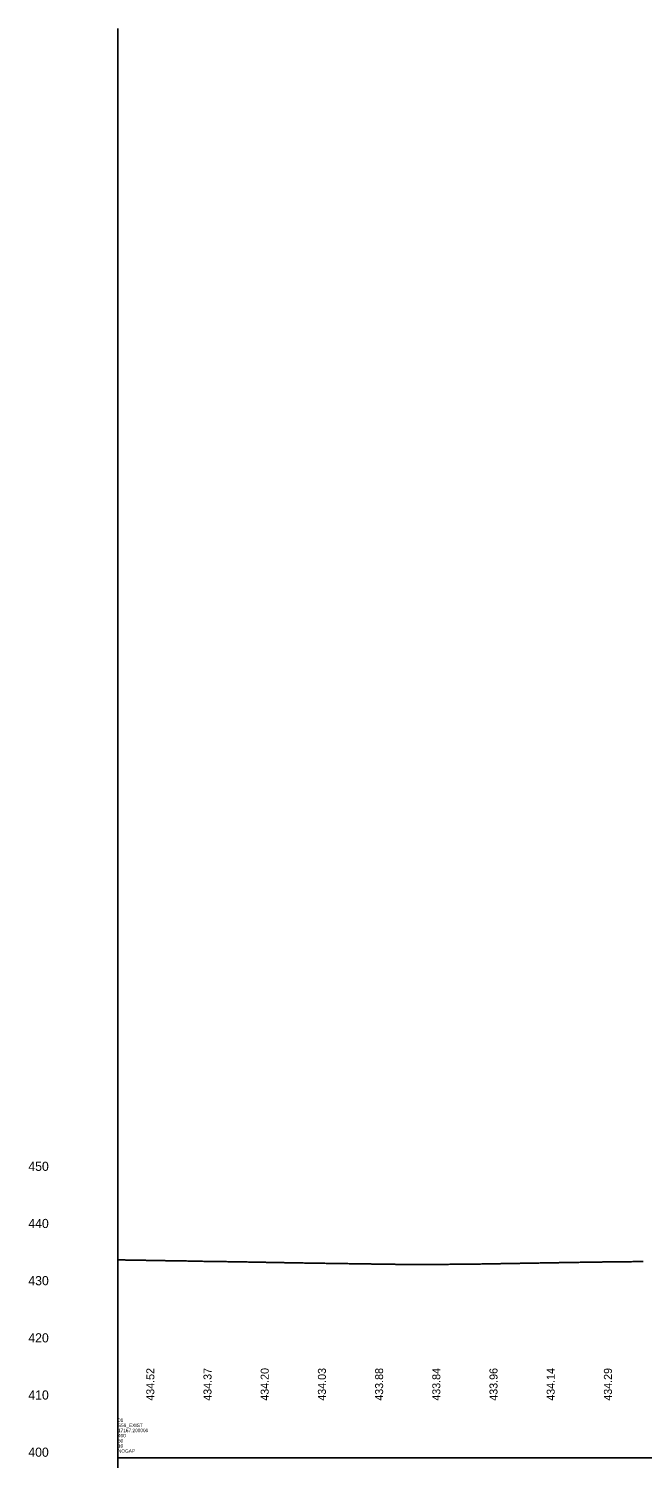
# Model space of a CAD drawing. Extents: x 1904865 to 1906752, y 1106408 to 1110518.
# Drawn here: x 1905174 to 1905711, y 1107657 to 1108908 of the extents above; entities that cross this region are included whole.
import ezdxf

# ---------------------------------------------------------------- set-up
doc = ezdxf.new("R2010")
doc.units = 0
for name, color, linetype in [('RD_DDB_ElevTX', 7, 'Continuous'), ('RD_DDB_Profile_EX', 7, 'Continuous'), ('RD_DDB_StripGrade', 7, 'Continuous'), ('RD_GPK_Profile_Cell', 7, 'Continuous')]:
    doc.layers.add(name, color=color, linetype=linetype)

msp = doc.modelspace()

# ---------------------------------------------------------------- linework, layer by layer
at = {"layer": 'RD_DDB_Profile_EX'}
for points in [[(1905252.2, 1107830.8), (1905253.2, 1107830.7), (1905254.2, 1107830.7), (1905255.2, 1107830.7), (1905256.2, 1107830.7), (1905257.2, 1107830.7), (1905258.2, 1107830.7), (1905259.2, 1107830.6), (1905260.2, 1107830.6), (1905261.2, 1107830.6), (1905262.2, 1107830.6), (1905263.2, 1107830.6), (1905264.2, 1107830.6), (1905265.2, 1107830.5), (1905266.2, 1107830.5), (1905267.2, 1107830.5), (1905268.2, 1107830.5), (1905269.2, 1107830.5), (1905270.2, 1107830.5), (1905271.2, 1107830.4), (1905272.2, 1107830.4), (1905273.2, 1107830.4), (1905274.2, 1107830.4), (1905275.2, 1107830.4), (1905276.2, 1107830.4), (1905277.2, 1107830.3), (1905278.2, 1107830.3), (1905279.2, 1107830.3), (1905280.2, 1107830.3), (1905281.2, 1107830.3), (1905282.2, 1107830.2), (1905283.2, 1107830.2), (1905284.2, 1107830.2), (1905285.2, 1107830.2), (1905286.2, 1107830.2), (1905287.2, 1107830.2), (1905288.2, 1107830.1), (1905289.2, 1107830.1), (1905290.2, 1107830.1), (1905291.2, 1107830.1), (1905292.2, 1107830.1), (1905293.2, 1107830.1), (1905294.2, 1107830), (1905295.2, 1107830), (1905296.2, 1107830), (1905297.2, 1107830), (1905298.2, 1107830), (1905299.2, 1107830), (1905300.2, 1107829.9), (1905301.2, 1107829.9), (1905302.2, 1107829.9), (1905303.2, 1107829.9), (1905304.2, 1107829.9), (1905305.2, 1107829.9), (1905306.2, 1107829.8), (1905307.2, 1107829.8), (1905308.2, 1107829.8), (1905309.2, 1107829.8), (1905310.2, 1107829.8), (1905311.2, 1107829.8), (1905312.2, 1107829.8), (1905313.2, 1107829.7), (1905314.2, 1107829.7), (1905315.2, 1107829.7), (1905316.2, 1107829.7), (1905317.2, 1107829.7), (1905318.2, 1107829.7), (1905319.2, 1107829.7), (1905320.2, 1107829.6), (1905321.2, 1107829.6), (1905322.2, 1107829.6), (1905323.2, 1107829.6), (1905324.2, 1107829.6), (1905325.2, 1107829.6), (1905326.2, 1107829.6), (1905327.2, 1107829.5), (1905328.2, 1107829.5), (1905329.2, 1107829.5), (1905330.2, 1107829.5), (1905331.2, 1107829.5), (1905332.2, 1107829.5), (1905333.2, 1107829.5), (1905334.2, 1107829.4), (1905335.2, 1107829.4), (1905336.2, 1107829.4), (1905337.2, 1107829.4), (1905338.2, 1107829.4), (1905339.2, 1107829.4), (1905340.2, 1107829.4), (1905341.2, 1107829.3), (1905342.2, 1107829.3), (1905343.2, 1107829.3), (1905344.2, 1107829.3), (1905345.2, 1107829.3), (1905346.2, 1107829.3), (1905347.2, 1107829.3), (1905348.2, 1107829.2), (1905349.2, 1107829.2), (1905350.2, 1107829.2), (1905351.2, 1107829.2), (1905352.2, 1107829.2)], [(1905352.2, 1107829.2), (1905353.2, 1107829.2), (1905354.2, 1107829.2), (1905355.2, 1107829.1), (1905356.2, 1107829.1), (1905357.2, 1107829.1), (1905358.2, 1107829.1), (1905359.2, 1107829.1), (1905360.2, 1107829.1), (1905361.2, 1107829), (1905362.2, 1107829), (1905363.2, 1107829), (1905364.2, 1107829), (1905365.2, 1107829), (1905366.2, 1107828.9), (1905367.2, 1107828.9), (1905368.2, 1107828.9), (1905369.2, 1107828.9), (1905370.2, 1107828.9), (1905371.2, 1107828.8), (1905372.2, 1107828.8), (1905373.2, 1107828.8), (1905374.2, 1107828.8), (1905375.2, 1107828.8), (1905376.2, 1107828.8), (1905377.2, 1107828.7), (1905378.2, 1107828.7), (1905379.2, 1107828.7), (1905380.2, 1107828.7), (1905381.2, 1107828.7), (1905382.2, 1107828.6), (1905383.2, 1107828.6), (1905384.2, 1107828.6), (1905385.2, 1107828.6), (1905386.2, 1107828.6), (1905387.2, 1107828.5), (1905388.2, 1107828.5), (1905389.2, 1107828.5), (1905390.2, 1107828.5), (1905391.2, 1107828.5), (1905392.2, 1107828.5), (1905393.2, 1107828.4), (1905394.2, 1107828.4), (1905395.2, 1107828.4), (1905396.2, 1107828.4), (1905397.2, 1107828.4), (1905398.2, 1107828.3), (1905399.2, 1107828.3), (1905400.2, 1107828.3), (1905401.2, 1107828.3), (1905402.2, 1107828.3), (1905403.2, 1107828.2), (1905404.2, 1107828.2), (1905405.2, 1107828.2), (1905406.2, 1107828.2), (1905407.2, 1107828.2), (1905408.2, 1107828.1), (1905409.2, 1107828.1), (1905410.2, 1107828.1), (1905411.2, 1107828.1), (1905412.2, 1107828.1), (1905413.2, 1107828.1), (1905414.2, 1107828.1), (1905415.2, 1107828), (1905416.2, 1107828), (1905417.2, 1107828), (1905418.2, 1107828), (1905419.2, 1107828), (1905420.2, 1107828), (1905421.2, 1107827.9), (1905422.2, 1107827.9), (1905423.2, 1107827.9), (1905424.2, 1107827.9), (1905425.2, 1107827.9), (1905426.2, 1107827.9), (1905427.2, 1107827.9), (1905428.2, 1107827.8), (1905429.2, 1107827.8), (1905430.2, 1107827.8), (1905431.2, 1107827.8), (1905432.2, 1107827.8), (1905433.2, 1107827.8), (1905434.2, 1107827.7), (1905435.2, 1107827.7), (1905436.2, 1107827.7), (1905437.2, 1107827.7), (1905438.2, 1107827.7), (1905439.2, 1107827.7), (1905440.2, 1107827.7), (1905441.2, 1107827.6), (1905442.2, 1107827.6), (1905443.2, 1107827.6), (1905444.2, 1107827.6), (1905445.2, 1107827.6), (1905446.2, 1107827.6), (1905447.2, 1107827.5), (1905448.2, 1107827.5), (1905449.2, 1107827.5), (1905450.2, 1107827.5), (1905451.2, 1107827.5), (1905452.2, 1107827.5)], [(1905552.2, 1107827), (1905553.2, 1107827), (1905554.2, 1107827), (1905555.2, 1107827), (1905556.2, 1107827), (1905557.2, 1107827), (1905558.2, 1107827), (1905559.2, 1107827), (1905560.2, 1107827), (1905561.2, 1107827), (1905562.2, 1107827), (1905563.2, 1107827.1), (1905564.2, 1107827.1), (1905565.2, 1107827.1), (1905566.2, 1107827.1), (1905567.2, 1107827.1), (1905568.2, 1107827.1), (1905569.2, 1107827.1), (1905570.2, 1107827.2), (1905571.2, 1107827.2), (1905572.2, 1107827.2), (1905573.2, 1107827.2), (1905574.2, 1107827.2), (1905575.2, 1107827.2), (1905576.2, 1107827.3), (1905577.2, 1107827.3), (1905578.2, 1107827.3), (1905579.2, 1107827.3), (1905580.2, 1107827.3), (1905581.2, 1107827.4), (1905582.2, 1107827.4), (1905583.2, 1107827.4), (1905584.2, 1107827.4), (1905585.2, 1107827.4), (1905586.2, 1107827.4), (1905587.2, 1107827.5), (1905588.2, 1107827.5), (1905589.2, 1107827.5), (1905590.2, 1107827.5), (1905591.2, 1107827.5), (1905592.2, 1107827.5), (1905593.2, 1107827.6), (1905594.2, 1107827.6), (1905595.2, 1107827.6), (1905596.2, 1107827.6), (1905597.2, 1107827.6), (1905598.2, 1107827.7), (1905599.2, 1107827.7), (1905600.2, 1107827.7), (1905601.2, 1107827.7), (1905602.2, 1107827.7), (1905603.2, 1107827.7), (1905604.2, 1107827.8), (1905605.2, 1107827.8), (1905606.2, 1107827.8), (1905607.2, 1107827.8), (1905608.2, 1107827.8), (1905609.2, 1107827.9), (1905610.2, 1107827.9), (1905611.2, 1107827.9), (1905612.2, 1107827.9), (1905613.2, 1107827.9), (1905614.2, 1107827.9), (1905615.2, 1107828), (1905616.2, 1107828), (1905617.2, 1107828), (1905618.2, 1107828), (1905619.2, 1107828), (1905620.2, 1107828), (1905621.2, 1107828.1), (1905622.2, 1107828.1), (1905623.2, 1107828.1), (1905624.2, 1107828.1), (1905625.2, 1107828.1), (1905626.2, 1107828.2), (1905627.2, 1107828.2), (1905628.2, 1107828.2), (1905629.2, 1107828.2), (1905630.2, 1107828.2), (1905631.2, 1107828.2), (1905632.2, 1107828.3), (1905633.2, 1107828.3), (1905634.2, 1107828.3), (1905635.2, 1107828.3), (1905636.2, 1107828.3), (1905637.2, 1107828.3), (1905638.2, 1107828.4), (1905639.2, 1107828.4), (1905640.2, 1107828.4), (1905641.2, 1107828.4), (1905642.2, 1107828.4), (1905643.2, 1107828.4), (1905644.2, 1107828.5), (1905645.2, 1107828.5), (1905646.2, 1107828.5), (1905647.2, 1107828.5), (1905648.2, 1107828.5), (1905649.2, 1107828.5), (1905650.2, 1107828.6), (1905651.2, 1107828.6), (1905652.2, 1107828.6)], [(1905652.2, 1107828.6), (1905653.2, 1107828.6), (1905654.2, 1107828.6), (1905655.2, 1107828.6), (1905656.2, 1107828.7), (1905657.2, 1107828.7), (1905658.2, 1107828.7), (1905659.2, 1107828.7), (1905660.2, 1107828.7), (1905661.2, 1107828.7), (1905662.2, 1107828.8), (1905663.2, 1107828.8), (1905664.2, 1107828.8), (1905665.2, 1107828.8), (1905666.2, 1107828.8), (1905667.2, 1107828.8), (1905668.2, 1107828.8), (1905669.2, 1107828.9), (1905670.2, 1107828.9), (1905671.2, 1107828.9), (1905672.2, 1107828.9), (1905673.2, 1107828.9), (1905674.2, 1107828.9), (1905675.2, 1107828.9), (1905676.2, 1107829), (1905677.2, 1107829), (1905678.2, 1107829), (1905679.2, 1107829), (1905680.2, 1107829), (1905681.2, 1107829), (1905682.2, 1107829), (1905683.2, 1107829), (1905684.2, 1107829), (1905685.2, 1107829.1), (1905686.2, 1107829.1), (1905687.2, 1107829.1), (1905688.2, 1107829.1), (1905689.2, 1107829.1), (1905690.2, 1107829.1), (1905691.2, 1107829.1), (1905692.2, 1107829.1), (1905693.2, 1107829.2), (1905694.2, 1107829.2), (1905695.2, 1107829.2), (1905696.2, 1107829.2), (1905697.2, 1107829.2), (1905698.2, 1107829.2), (1905699.2, 1107829.2), (1905700.2, 1107829.2), (1905701.2, 1107829.2), (1905702.2, 1107829.3), (1905703.2, 1107829.3), (1905704.2, 1107829.3), (1905705.2, 1107829.3), (1905706.2, 1107829.3), (1905707.2, 1107829.3), (1905708.2, 1107829.3), (1905709.2, 1107829.3), (1905710.2, 1107829.4), (1905711.2, 1107829.4)], [(1905452.2, 1107827.5), (1905453.2, 1107827.5), (1905454.2, 1107827.4), (1905455.2, 1107827.4), (1905456.2, 1107827.4), (1905457.2, 1107827.4), (1905458.2, 1107827.4), (1905459.2, 1107827.4), (1905460.2, 1107827.3), (1905461.2, 1107827.3), (1905462.2, 1107827.3), (1905463.2, 1107827.3), (1905464.2, 1107827.3), (1905465.2, 1107827.3), (1905466.2, 1107827.3), (1905467.2, 1107827.3), (1905468.2, 1107827.2), (1905469.2, 1107827.2), (1905470.2, 1107827.2), (1905471.2, 1107827.2), (1905472.2, 1107827.2), (1905473.2, 1107827.2), (1905474.2, 1107827.1), (1905475.2, 1107827.1), (1905476.2, 1107827.1), (1905477.2, 1107827.1), (1905478.2, 1107827.1), (1905479.2, 1107827.1), (1905480.2, 1107827.1), (1905481.2, 1107827), (1905482.2, 1107827), (1905483.2, 1107827), (1905484.2, 1107827), (1905485.2, 1107827), (1905486.2, 1107827), (1905487.2, 1107827), (1905488.2, 1107826.9), (1905489.2, 1107826.9), (1905490.2, 1107826.9), (1905491.2, 1107826.9), (1905492.2, 1107826.9), (1905493.2, 1107826.9), (1905494.2, 1107826.9), (1905495.2, 1107826.8), (1905496.2, 1107826.8), (1905497.2, 1107826.8), (1905498.2, 1107826.8), (1905499.2, 1107826.8), (1905500.2, 1107826.8), (1905501.2, 1107826.7), (1905502.2, 1107826.7), (1905503.2, 1107826.7), (1905504.2, 1107826.7), (1905505.2, 1107826.7), (1905506.2, 1107826.7), (1905507.2, 1107826.7), (1905508.2, 1107826.6), (1905509.2, 1107826.6), (1905510.2, 1107826.6), (1905511.2, 1107826.6), (1905512.2, 1107826.6), (1905513.2, 1107826.6), (1905514.2, 1107826.6), (1905515.2, 1107826.6), (1905516.2, 1107826.6), (1905517.2, 1107826.6), (1905518.2, 1107826.6), (1905519.2, 1107826.6), (1905520.2, 1107826.6), (1905521.2, 1107826.7), (1905522.2, 1107826.7), (1905523.2, 1107826.7), (1905524.2, 1107826.7), (1905525.2, 1107826.7), (1905526.2, 1107826.7), (1905527.2, 1107826.7), (1905528.2, 1107826.7), (1905529.2, 1107826.7), (1905530.2, 1107826.7), (1905531.2, 1107826.8), (1905532.2, 1107826.8), (1905533.2, 1107826.8), (1905534.2, 1107826.8), (1905535.2, 1107826.8), (1905536.2, 1107826.8), (1905537.2, 1107826.8), (1905538.2, 1107826.8), (1905539.2, 1107826.8), (1905540.2, 1107826.8), (1905541.2, 1107826.8), (1905542.2, 1107826.9), (1905543.2, 1107826.9), (1905544.2, 1107826.9), (1905545.2, 1107826.9), (1905546.2, 1107826.9), (1905547.2, 1107826.9), (1905548.2, 1107826.9), (1905549.2, 1107826.9), (1905550.2, 1107826.9), (1905551.2, 1107826.9), (1905552.2, 1107827)]]:
    msp.add_lwpolyline(points, dxfattribs=at)
at = {"layer": 'RD_GPK_Profile_Cell'}
for q in [(1905252.2, 1108907.6), (1906752.2, 1107657.6), (1905252.2, 1106407.6)]:
    msp.add_line((1905252.2, 1107657.6), q, dxfattribs=at)

# ---------------------------------------------------------------- texts
at = {"layer": 'RD_DDB_ElevTX'}
for s, p in [('450', (1905173.9, 1107908.6)), ('440', (1905173.9, 1107858.6)), ('430', (1905173.9, 1107808.6)), ('420', (1905173.9, 1107758.6)), ('410', (1905173.9, 1107708.6)), ('400', (1905173.9, 1107658.6))]:
    msp.add_text(s, height=8, dxfattribs=at).set_placement(p)
at = {"layer": 'RD_DDB_StripGrade'}
for s, p in [('434.52', (1905284, 1107707.6)), ('434.37', (1905334, 1107707.6)), ('434.20', (1905384, 1107707.6)), ('434.03', (1905434, 1107707.6)), ('433.88', (1905484, 1107707.6)), ('433.84', (1905534, 1107707.6)), ('433.96', (1905584, 1107707.6)), ('434.14', (1905634, 1107707.6)), ('434.29', (1905684, 1107707.6))]:
    msp.add_text(s, height=7, rotation=90, dxfattribs=at).set_placement(p)
at = {"layer": 'RD_GPK_Profile_Cell'}
for s, p in [('01', (1905252.2, 1107689.1)), ('400', (1905252.2, 1107675.6)), ('S59_EXIST', (1905252.2, 1107684.6)), ('17167.200000', (1905252.2, 1107680.1)), ('50', (1905252.2, 1107671.1)), ('10', (1905252.2, 1107666.6)), ('NOGAP', (1905252.2, 1107662.1))]:
    msp.add_text(s, height=3, dxfattribs=at).set_placement(p)

doc.saveas('drawing.dxf')
